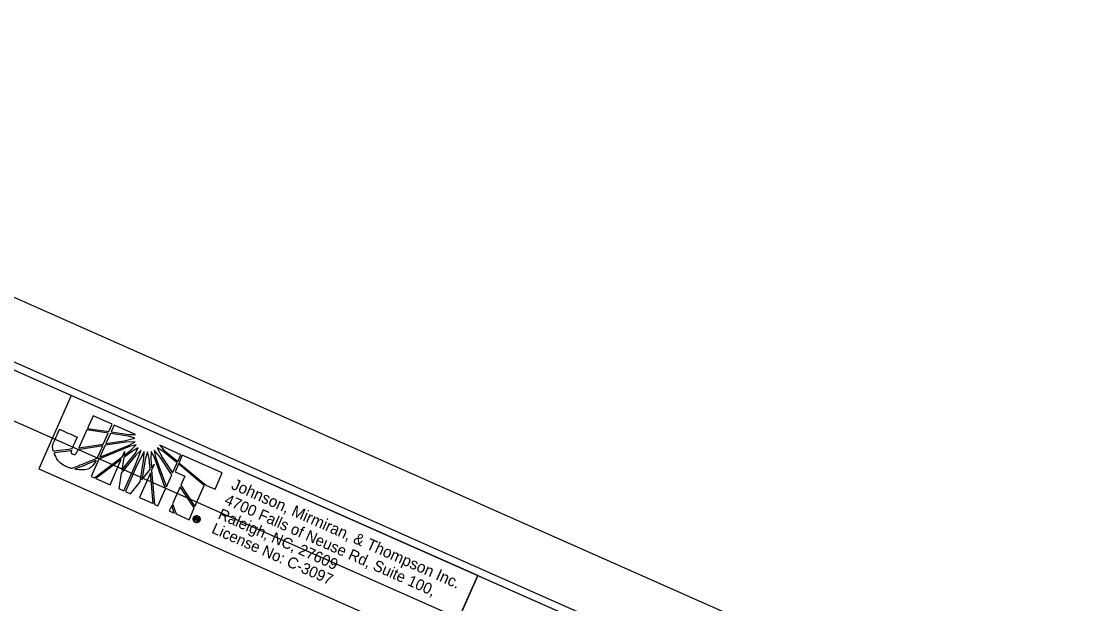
# Model space of a CAD drawing. Extents: x 1637682 to 2864602, y 842496 to 973236.
# Drawn here: x 1639303.7 to 1639665.2, y 843555.1 to 843751.6 of the extents above; entities that cross this region are included whole.
import ezdxf

# ---------------------------------------------------------------- set-up
doc = ezdxf.new("R2010")
doc.units = 0
for name, color, linetype in [('Prop Dimension Text', 7, 'Continuous'), ('Sheet Clip Boundary CELL', 7, 'Continuous'), ('Sheet Plan CELL', 7, 'Continuous'), ('Sheet Plot Border Inside CELL', 7, 'Continuous'), ('Sheet Plot Border Outside CELL', 7, 'Continuous')]:
    doc.layers.add(name, color=color, linetype=linetype)

msp = doc.modelspace()

# ---------------------------------------------------------------- linework, layer by layer
at = {"layer": 'Prop Dimension Text'}
for p, q in [((1639327.85, 843618.43), (1639325.97, 843614.17)), ((1639334.27, 843615.59), (1639327.85, 843618.43)), ((1639333.17, 843613.11), (1639334.27, 843615.59)), ((1639334.95, 843615.33), (1639333.93, 843613.03)), ((1639342.18, 843612.13), (1639334.95, 843615.33)), ((1639325.75, 843613.69), (1639323.1, 843607.7)), ((1639332.97, 843612.65), (1639325.75, 843613.69)), ((1639325.97, 843614.17), (1639333.17, 843613.11)), ((1639331.32, 843608.93), (1639332.97, 843612.65)), ((1639333.71, 843612.53), (1639332.18, 843609.06)), ((1639339.75, 843611.64), (1639333.71, 843612.53)), ((1639333.93, 843613.03), (1639339.97, 843612.13)), ((1639338.35, 843609.98), (1639341.96, 843610.96)), ((1639341.96, 843610.96), (1639339.75, 843611.64)), ((1639339.97, 843612.13), (1639342.18, 843612.13)), ((1639323.1, 843607.7), (1639331.32, 843608.93)), ((1639340.17, 843608.07), (1639329.86, 843603.81)), ((1639330.16, 843604.49), (1639340.04, 843608.54)), ((1639331.93, 843608.5), (1639330.16, 843604.49)), ((1639339.06, 843609.57), (1639331.93, 843608.5)), ((1639332.18, 843609.06), (1639338.35, 843609.98)), ((1639342.05, 843609.73), (1639339.06, 843609.57)), ((1639340.04, 843608.54), (1639342.05, 843609.73)), ((1639342.45, 843608.63), (1639340.17, 843608.07)), ((1639340.76, 843606.92), (1639342.45, 843608.63)), ((1639343.12, 843607.65), (1639341.13, 843606.58)), ((1639342.06, 843605.75), (1639343.12, 843607.65)), ((1639349.53, 843607.62), (1639351.25, 843604.22)), ((1639351.4, 843606.49), (1639349.53, 843607.62)), ((1639357.46, 843605.34), (1639350.36, 843608.52)), ((1639350.36, 843608.52), (1639351.78, 843606.87)), ((1639329.86, 843603.81), (1639327.28, 843597.98)), ((1639328.34, 843597.52), (1639337.78, 843604.68)), ((1639337.37, 843603.76), (1639328.84, 843597.3)), ((1639333.63, 843595.18), (1639337.37, 843603.76)), ((1639342.27, 843605.23), (1639337.38, 843599.09)), ((1639337.57, 843600.07), (1639342.06, 843605.75)), ((1639338.24, 843604.39), (1639337.57, 843600.07)), ((1639337.78, 843604.68), (1639338.53, 843606.38)), ((1639341.13, 843606.58), (1639338.24, 843604.39)), ((1639338.33, 843605.07), (1639340.76, 843606.92)), ((1639338.53, 843606.38), (1639338.33, 843605.07)), ((1639342.09, 843601.71), (1639344.05, 843606.9)), ((1639344.05, 843606.9), (1639342.27, 843605.23)), ((1639345.11, 843606.43), (1639342.55, 843601.51)), ((1639343.78, 843596.14), (1639345.05, 843604)), ((1639345.57, 843604.11), (1639344.37, 843596.89)), ((1639345.05, 843604), (1639345.11, 843606.43)), ((1639346.27, 843606.26), (1639345.57, 843604.11)), ((1639346.79, 843604.08), (1639346.27, 843606.26)), ((1639347.12, 843600.33), (1639346.79, 843604.08)), ((1639347.43, 843606.43), (1639347.31, 843604.03)), ((1639347.31, 843604.03), (1639347.56, 843600.86)), ((1639348.56, 843604.36), (1639347.43, 843606.43)), ((1639348.53, 843606.87), (1639348.98, 843604.55)), ((1639350.46, 843604.53), (1639348.53, 843606.87)), ((1639352.31, 843593.8), (1639348.56, 843604.36)), ((1639348.98, 843604.55), (1639352.61, 843594.47)), ((1639354.43, 843598.58), (1639350.46, 843604.53)), ((1639351.25, 843604.22), (1639354.68, 843599.16)), ((1639356.23, 843602.54), (1639351.4, 843606.49)), ((1639351.78, 843606.87), (1639356.44, 843603.03)), ((1639356.44, 843603.03), (1639357.46, 843605.34)), ((1639357.98, 843605.15), (1639356.88, 843602.67)), ((1639371.48, 843599.18), (1639357.98, 843605.15)), ((1639338.3, 843593.15), (1639342.09, 843601.71)), ((1639342.55, 843601.51), (1639338.76, 843592.95)), ((1639344.37, 843596.89), (1639347.12, 843600.33)), ((1639347.56, 843600.86), (1639348.45, 843601.99)), ((1639348.45, 843601.99), (1639347.62, 843600.11)), ((1639347.62, 843600.11), (1639348.63, 843588.54)), ((1639354.68, 843599.16), (1639356.23, 843602.54)), ((1639356.66, 843602.17), (1639355.52, 843599.58)), ((1639356.68, 843602.21), (1639356.66, 843602.17)), ((1639365.37, 843594.97), (1639356.68, 843602.21)), ((1639356.88, 843602.67), (1639356.85, 843602.59)), ((1639356.85, 843602.59), (1639366.16, 843594.92)), ((1639327.28, 843597.98), (1639328.34, 843597.52)), ((1639328.84, 843597.3), (1639333.63, 843595.18)), ((1639337.38, 843599.09), (1639336.54, 843593.93)), ((1639347.21, 843599.19), (1639343.52, 843590.84)), ((1639348.12, 843588.81), (1639347.21, 843599.19)), ((1639352.61, 843594.47), (1639354.43, 843598.58)), ((1639355.52, 843599.58), (1639358.81, 843598.13)), ((1639358.81, 843598.13), (1639357.45, 843595.04)), ((1639369.03, 843593.65), (1639371.48, 843599.18)), ((1639336.54, 843593.93), (1639338.3, 843593.15)), ((1639338.76, 843592.95), (1639340.54, 843592.16)), ((1639340.54, 843592.16), (1639343.78, 843596.14)), ((1639349.76, 843588.04), (1639352.31, 843593.8)), ((1639357.21, 843594.51), (1639354.67, 843588.77)), ((1639362.02, 843587.39), (1639357.21, 843594.51)), ((1639357.45, 843595.04), (1639362.24, 843587.88)), ((1639362.24, 843587.88), (1639365.37, 843594.97)), ((1639366.16, 843594.92), (1639369.03, 843593.65)), ((1639343.52, 843590.84), (1639348.12, 843588.81)), ((1639348.63, 843588.54), (1639349.76, 843588.04)), ((1639354.4, 843588.15), (1639353.6, 843586.34)), ((1639353.6, 843586.34), (1639355.26, 843585.61)), ((1639355.26, 843585.61), (1639354.4, 843588.15)), ((1639354.67, 843588.77), (1639355.9, 843585.33)), ((1639360.25, 843583.4), (1639362.02, 843587.39)), ((1639355.9, 843585.33), (1639360.25, 843583.4)), ((1639362.21, 843583.26), (1639362.65, 843584.24)), ((1639362.44, 843583.16), (1639362.21, 843583.26)), ((1639362.45, 843582.7), (1639362.35, 843582.48)), ((1639362.35, 843582.48), (1639362.45, 843582.7)), ((1639362.36, 843582.48), (1639362.35, 843582.48)), ((1639362.61, 843583.55), (1639362.44, 843583.16)), ((1639362.45, 843582.7), (1639362.45, 843582.69)), ((1639362.78, 843583.47), (1639362.61, 843583.55)), ((1639362.65, 843584.24), (1639363.05, 843584.06)), ((1639362.79, 843583.96), (1639362.68, 843583.72)), ((1639362.68, 843583.72), (1639362.86, 843583.64)), ((1639362.86, 843583.64), (1639362.78, 843583.47)), ((1639362.78, 843583.47), (1639362.86, 843583.64)), ((1639362.79, 843583.46), (1639362.78, 843583.47)), ((1639362.97, 843583.88), (1639362.79, 843583.96)), ((1639362.86, 843583.64), (1639362.87, 843583.64)), ((1639363.05, 843584.06), (1639362.97, 843583.88)), ((1639362.97, 843583.88), (1639363.05, 843584.06)), ((1639362.99, 843583.86), (1639362.97, 843583.88)), ((1639363.05, 843584.06), (1639363.11, 843584.04)), ((1639363.31, 843584.64), (1639363.21, 843584.44)), ((1639363.21, 843584.44), (1639363.31, 843584.64))]:
    msp.add_line(p, q, dxfattribs=at)
msp.add_lwpolyline([(1639309.54, 843600.57), (1639446.69, 843539.76), (1639457.67, 843564.51), (1639320.52, 843625.32)], close=True, dxfattribs=at)
for points in [[(1639325.97, 843614.17), (1639333.17, 843613.11), (1639334.27, 843615.59), (1639327.85, 843618.43), (1639325.97, 843614.17)], [(1639339.97, 843612.13), (1639342.18, 843612.13), (1639334.95, 843615.33), (1639333.93, 843613.03), (1639339.97, 843612.13)], [(1639323.1, 843607.7), (1639331.32, 843608.93), (1639332.97, 843612.65), (1639325.75, 843613.69), (1639323.1, 843607.7)], [(1639333.71, 843612.53), (1639332.18, 843609.06), (1639338.35, 843609.98), (1639341.96, 843610.96), (1639339.75, 843611.64), (1639333.71, 843612.53)], [(1639342.45, 843608.63), (1639340.17, 843608.07), (1639329.86, 843603.81), (1639327.28, 843597.98), (1639328.34, 843597.52), (1639337.78, 843604.68), (1639338.53, 843606.38), (1639338.33, 843605.07), (1639340.76, 843606.92), (1639342.45, 843608.63)], [(1639331.93, 843608.5), (1639330.16, 843604.49), (1639340.04, 843608.54), (1639342.05, 843609.73), (1639339.06, 843609.57), (1639331.93, 843608.5)], [(1639343.12, 843607.65), (1639341.13, 843606.58), (1639338.24, 843604.39), (1639337.57, 843600.07), (1639342.06, 843605.75), (1639343.12, 843607.65)], [(1639349.53, 843607.62), (1639351.25, 843604.22), (1639354.68, 843599.16), (1639356.23, 843602.54), (1639351.4, 843606.49), (1639349.53, 843607.62)], [(1639351.78, 843606.87), (1639356.44, 843603.03), (1639357.46, 843605.34), (1639350.36, 843608.52), (1639351.78, 843606.87)], [(1639328.84, 843597.3), (1639333.63, 843595.18), (1639337.37, 843603.76), (1639328.84, 843597.3)], [(1639342.27, 843605.23), (1639337.38, 843599.09), (1639336.54, 843593.93), (1639338.3, 843593.15), (1639342.09, 843601.71), (1639344.05, 843606.9), (1639342.27, 843605.23)], [(1639345.11, 843606.43), (1639342.55, 843601.51), (1639338.76, 843592.95), (1639340.54, 843592.16), (1639343.78, 843596.14), (1639345.05, 843604), (1639345.11, 843606.43)], [(1639346.27, 843606.26), (1639345.57, 843604.11), (1639344.37, 843596.89), (1639347.12, 843600.33), (1639346.79, 843604.08), (1639346.27, 843606.26)], [(1639347.43, 843606.43), (1639347.31, 843604.03), (1639347.56, 843600.86), (1639348.45, 843601.99), (1639347.62, 843600.11), (1639348.63, 843588.54), (1639349.76, 843588.04), (1639352.31, 843593.8), (1639348.56, 843604.36), (1639347.43, 843606.43)], [(1639348.53, 843606.87), (1639348.98, 843604.55), (1639352.61, 843594.47), (1639354.43, 843598.58), (1639350.46, 843604.53), (1639348.53, 843606.87)], [(1639371.48, 843599.18), (1639357.98, 843605.15), (1639356.88, 843602.67), (1639356.85, 843602.59), (1639366.16, 843594.92), (1639369.03, 843593.65), (1639371.48, 843599.18)], [(1639356.68, 843602.21), (1639356.66, 843602.17), (1639355.52, 843599.58), (1639358.81, 843598.13), (1639357.45, 843595.04), (1639362.24, 843587.88), (1639365.37, 843594.97), (1639356.68, 843602.21)], [(1639343.52, 843590.84), (1639348.12, 843588.81), (1639347.21, 843599.19), (1639343.52, 843590.84)], [(1639357.21, 843594.51), (1639354.67, 843588.77), (1639355.9, 843585.33), (1639360.25, 843583.4), (1639362.02, 843587.39), (1639357.21, 843594.51), (1639357.21, 843594.51)], [(1639353.6, 843586.34), (1639353.6, 843586.34), (1639355.26, 843585.61), (1639354.4, 843588.15), (1639353.6, 843586.34)], [(1639363.15, 843583.12), (1639363.12, 843583.07), (1639363.11, 843583.03), (1639363.1, 843583), (1639363.08, 843582.88), (1639362.87, 843582.97)]]:
    msp.add_lwpolyline(points, dxfattribs=at)
for points, degree in [([(1639322.48, 843611.27), (1639322.48, 843611.27), (1639316.53, 843613.9), (1639316.53, 843613.9), (1639316.53, 843613.9), (1639314.89, 843610.18), (1639314.89, 843610.18), (1639314.89, 843610.18), (1639314.71, 843609.79), (1639314.71, 843609.79), (1639314.2, 843608.62), (1639314.17, 843607.53), (1639314.51, 843606.46), (1639314.51, 843606.46), (1639320.71, 843607.26), (1639320.74, 843607.34), (1639320.74, 843607.34), (1639322.48, 843611.27), (1639322.48, 843611.27)], 3), ([(1639321.03, 843605.51), (1639320.65, 843605.68), (1639320.42, 843606.04), (1639320.59, 843606.81), (1639320.59, 843606.81), (1639314.72, 843606), (1639314.72, 843606), (1639315.48, 843603.87), (1639317.36, 843601.98), (1639319.27, 843601.13), (1639319.77, 843600.91), (1639320.17, 843600.79), (1639320.75, 843600.66), (1639320.75, 843600.66), (1639329.18, 843604.08), (1639329.18, 843604.08), (1639329.18, 843604.08), (1639331.09, 843608.4), (1639331.09, 843608.4), (1639331.09, 843608.4), (1639322.86, 843607.16), (1639322.86, 843607.16), (1639322.15, 843605.54), (1639321.56, 843605.28), (1639321.03, 843605.51)], 3), ([(1639321.03, 843605.51), (1639320.65, 843605.68), (1639320.42, 843606.04), (1639320.59, 843606.81), (1639320.59, 843606.81), (1639314.72, 843606), (1639314.72, 843606), (1639315.48, 843603.87), (1639317.36, 843601.98), (1639319.27, 843601.13), (1639319.77, 843600.91), (1639320.17, 843600.79), (1639320.75, 843600.66), (1639320.75, 843600.66), (1639329.18, 843604.08), (1639329.18, 843604.08), (1639329.18, 843604.08), (1639331.09, 843608.4), (1639331.09, 843608.4), (1639331.09, 843608.4), (1639322.86, 843607.16), (1639322.86, 843607.16), (1639322.15, 843605.54), (1639321.56, 843605.28), (1639321.03, 843605.51)], 3), ([(1639328.88, 843603.4), (1639328.88, 843603.4), (1639321.59, 843600.45), (1639321.59, 843600.45), (1639324.31, 843599.97), (1639327.46, 843600.51), (1639328.88, 843603.4)], 3), ([(1639362.35, 843582.48), (1639362.06, 843582.61), (1639361.84, 843582.84), (1639361.72, 843583.15), (1639361.6, 843583.45), (1639361.61, 843583.75), (1639361.74, 843584.05), (1639361.88, 843584.36), (1639362.1, 843584.57), (1639362.4, 843584.67), (1639362.7, 843584.78), (1639363, 843584.78), (1639363.31, 843584.64)], 3), ([(1639363.21, 843584.44), (1639362.97, 843584.55), (1639362.73, 843584.56), (1639362.49, 843584.47), (1639362.25, 843584.38), (1639362.06, 843584.2), (1639361.96, 843583.96), (1639361.85, 843583.72), (1639361.85, 843583.47), (1639361.94, 843583.22), (1639362.03, 843582.98), (1639362.2, 843582.81), (1639362.45, 843582.7)], 3), ([(1639363.93, 843583.09), (1639363.8, 843582.78), (1639363.57, 843582.57), (1639363.27, 843582.45), (1639362.97, 843582.34), (1639362.66, 843582.35), (1639362.36, 843582.48)], 3), ([(1639362.45, 843582.69), (1639362.69, 843582.59), (1639362.94, 843582.58), (1639363.18, 843582.67), (1639363.42, 843582.77), (1639363.61, 843582.94), (1639363.72, 843583.18), (1639363.82, 843583.42), (1639363.83, 843583.68), (1639363.73, 843583.92), (1639363.63, 843584.16), (1639363.46, 843584.33), (1639363.21, 843584.44)], 3), ([(1639362.95, 843583.35), (1639362.93, 843583.38), (1639362.88, 843583.42), (1639362.79, 843583.46)], 2), ([(1639362.87, 843583.64), (1639363.01, 843583.58), (1639363.11, 843583.59), (1639363.14, 843583.67), (1639363.17, 843583.74), (1639363.13, 843583.81), (1639362.99, 843583.86)], 3), ([(1639362.87, 843582.97), (1639362.87, 843583.03), (1639362.88, 843583.09), (1639362.91, 843583.17), (1639362.95, 843583.26), (1639362.96, 843583.31), (1639362.95, 843583.35)], 3), ([(1639363.11, 843584.04), (1639363.36, 843583.93), (1639363.44, 843583.77), (1639363.36, 843583.58), (1639363.32, 843583.49), (1639363.25, 843583.43), (1639363.15, 843583.41)], 3), ([(1639363.15, 843583.41), (1639363.19, 843583.35), (1639363.19, 843583.25), (1639363.15, 843583.12)], 2), ([(1639363.31, 843584.64), (1639363.61, 843584.51), (1639363.82, 843584.29), (1639363.94, 843583.99), (1639364.07, 843583.7), (1639364.06, 843583.39), (1639363.93, 843583.09)], 3)]:
    msp.add_open_spline(points, degree=degree, dxfattribs=at)
at = {"layer": 'Sheet Clip Boundary CELL'}
msp.add_lwpolyline([(1638095.26, 843695.55), (1638010.34, 843303.19), (1637949.73, 843324.57), (1637886.34, 843167.39), (1638760.91, 842777.56), (1638750.92, 842749.91), (1638861.21, 842700.69), (1639015.67, 842665.82), (1639189.46, 842589.52), (1639522.76, 843341.19), (1639380.4, 843404.31), (1639446.06, 843552.39), (1639089.07, 843710.68), (1638988.3, 843567.43), (1638956.05, 843552.43), (1638629.84, 843695.47), (1638719.07, 843884.38), (1638267, 844086.34)], close=True, dxfattribs=at)
at = {"layer": 'Sheet Plan CELL'}
for points in [[(1639640.56, 843483.39), (1638269.28, 844091.43), (1637843.67, 843131.56), (1639214.92, 842523.53)], [(1637843.67, 843131.56), (1638269.25, 844091.42), (1639457.67, 843564.51), (1639396.85, 843427.32), (1639579.71, 843346.22), (1639214.92, 842523.53)], [(1639457.67, 843564.51), (1639640.56, 843483.39), (1639630.37, 843460.51), (1639447.5, 843541.57)]]:
    msp.add_lwpolyline(points, close=True, dxfattribs=at)
at = {"layer": 'Sheet Plot Border Inside CELL'}
msp.add_lwpolyline([(1637702.34, 843191.48), (1639225.33, 842516.19), (1639652.97, 843480.61), (1638129.98, 844155.92)], close=True, dxfattribs=at)
at = {"layer": 'Sheet Plot Border Outside CELL'}
msp.add_lwpolyline([(1637682.35, 843178.46), (1639221.34, 842496.06), (1639665.19, 843497.07), (1638126.2, 844179.47)], close=True, dxfattribs=at)
msp.add_lwpolyline([(1637682.35, 843178.46), (1639221.34, 842496.06), (1639665.19, 843497.07), (1638126.2, 844179.47)], close=True, dxfattribs=at)

# ---------------------------------------------------------------- texts
at = {"layer": 'Prop Dimension Text'}
for s, height, p in [('Johnson, Mirmiran, & Thompson Inc.', 3.8334, (1639374.19, 843593.94)), ('4700 Falls of Neuse Rd, Suite 100, ', 3.7239, (1639371.91, 843588.79)), ('Raleigh, NC, 27609', 3.7239, (1639369.75, 843583.93)), ('License No: C-3097', 3.7239, (1639367.59, 843579.07))]:
    msp.add_text(s, height=height, rotation=336.0871, dxfattribs=at).set_placement(p)

doc.saveas('drawing.dxf')
